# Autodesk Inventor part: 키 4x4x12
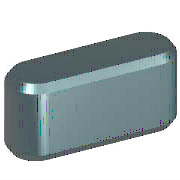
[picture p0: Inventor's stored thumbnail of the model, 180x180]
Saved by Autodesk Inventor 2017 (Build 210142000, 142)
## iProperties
IsCustomPart: 1
Created: 2012-02
Part Number: 키 4x4x12
Material: 강철, 연강
Description: 키 및 해당 키홈
Document SubType Name: Modeling
Standard: KS B 1311
Designer: mduedu
Standards Organization: KS
Language: ko-KR
Size Designation: 4 x 4 x 12
Categories: <MemberInstance><Categories><Category DisplayName="샤프트 부품" InternalName="7f7aeb1f-a693-4053-b835-cee3144e0d98" Mnemonic="SHFT"><Category DisplayName="키" Interna
Density: 7.85 g/cm^3
Mass: 1.38563 g
Surface Area: 1.94869 cm^2
Volume: 0.176513 cm^3
Appearance: 노란색
Author: mduedu
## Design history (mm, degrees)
workplane "Work Plane1"
workplane "Work Plane2"
sketch "스케치1"
  geometry: L1 (2, 2)-(10, 2); L2 (10, -2)-(2, -2); L3 (0, 9.4)-(0, -7.4) reference; L4 (-5, 0)-(30, 0) reference; L5 (12, 0)-(12, 7); A1 r 2 centre (2, 0) between (2, 2) and (2, -2); A2 r 2 centre (10, 0) between (10, -2) and (10, 2)
  constraints: 6 end point, 5 point on circle, 4 tangent, 3 point on line, 2 centre point, 1 horizontal, 1 parallel, 1 perpendicular
  dimensions: "d0" = 2 radius of A1 (= 0.5 x PB); "d13" = 2 radius of A2 (= 0.5 x PB); "d14" = 12 distance between parallel lines of L5 L3 (= NLG)
extrude "본체1" new body sketch "스케치1" taper "d3" = 0 deg; stored distance "d4" = 10
workplane "Work Plane3"
body "Solid1"
chamfer "모따기1" distance "d8" = 0.25 (= PHH); stored, may be unused: second distance "d9" = 0.25 (= PHH), angle "d15" = 45 deg
other parameters: "d1" = -2.5 (= -PNT), "d2" = 1.5 (= PH - PNT), "NLG" = 12 [user parameter; used in 3 equation terms], "PB" = 4 [user parameter; used in 2 equation terms], "PNT" = 2.5 [user parameter; used in 2 equation terms], "PH" = 4 [user parameter; used in 1 equation term], "PHH" = 0.25 [user parameter; used in 2 equation terms], "d10" = 0, "d16" = 0, "d17" = 0, "d18" = 0, "PLB2" = 12 (= NLG) [user parameter], "WDMAX" = 12 [user parameter], "PLB1" = 12 (= NLG) [user parameter], "RR" = 0.08 [user parameter], "PUEB" = 1.8 [user parameter]
